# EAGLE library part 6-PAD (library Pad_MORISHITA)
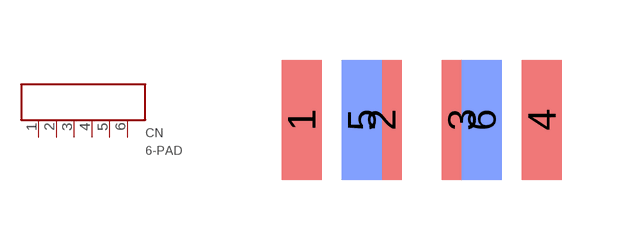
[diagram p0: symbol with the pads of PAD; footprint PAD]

Designator prefix CN

## 6-PAD  [PAD]
1  P$1
2  P$2
3  P$3
4  P$4
5  P$5
6  P$6

## Footprint PAD (pad centres in mm)
smd 1 x 3: 1 -3,0; 2 -1,0; 3 1,0; 4 3,0
smd 1 x 3 bottom: 5 -1.5,0; 6 1.5,0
